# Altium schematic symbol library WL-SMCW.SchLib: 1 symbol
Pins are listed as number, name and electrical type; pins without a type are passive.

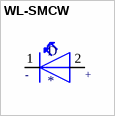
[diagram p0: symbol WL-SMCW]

## WL-SMCW
designator D
Green 520nm LED Indication - Discrete 3.2V 0805 _2012 Metric_; MF: Wurth Electronics; MP: 150080GS75000
footprint WL-SMCW_0805
pins: 1 NEG (io), 2 POS (io)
